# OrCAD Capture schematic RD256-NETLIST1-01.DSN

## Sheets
1 3: size A3
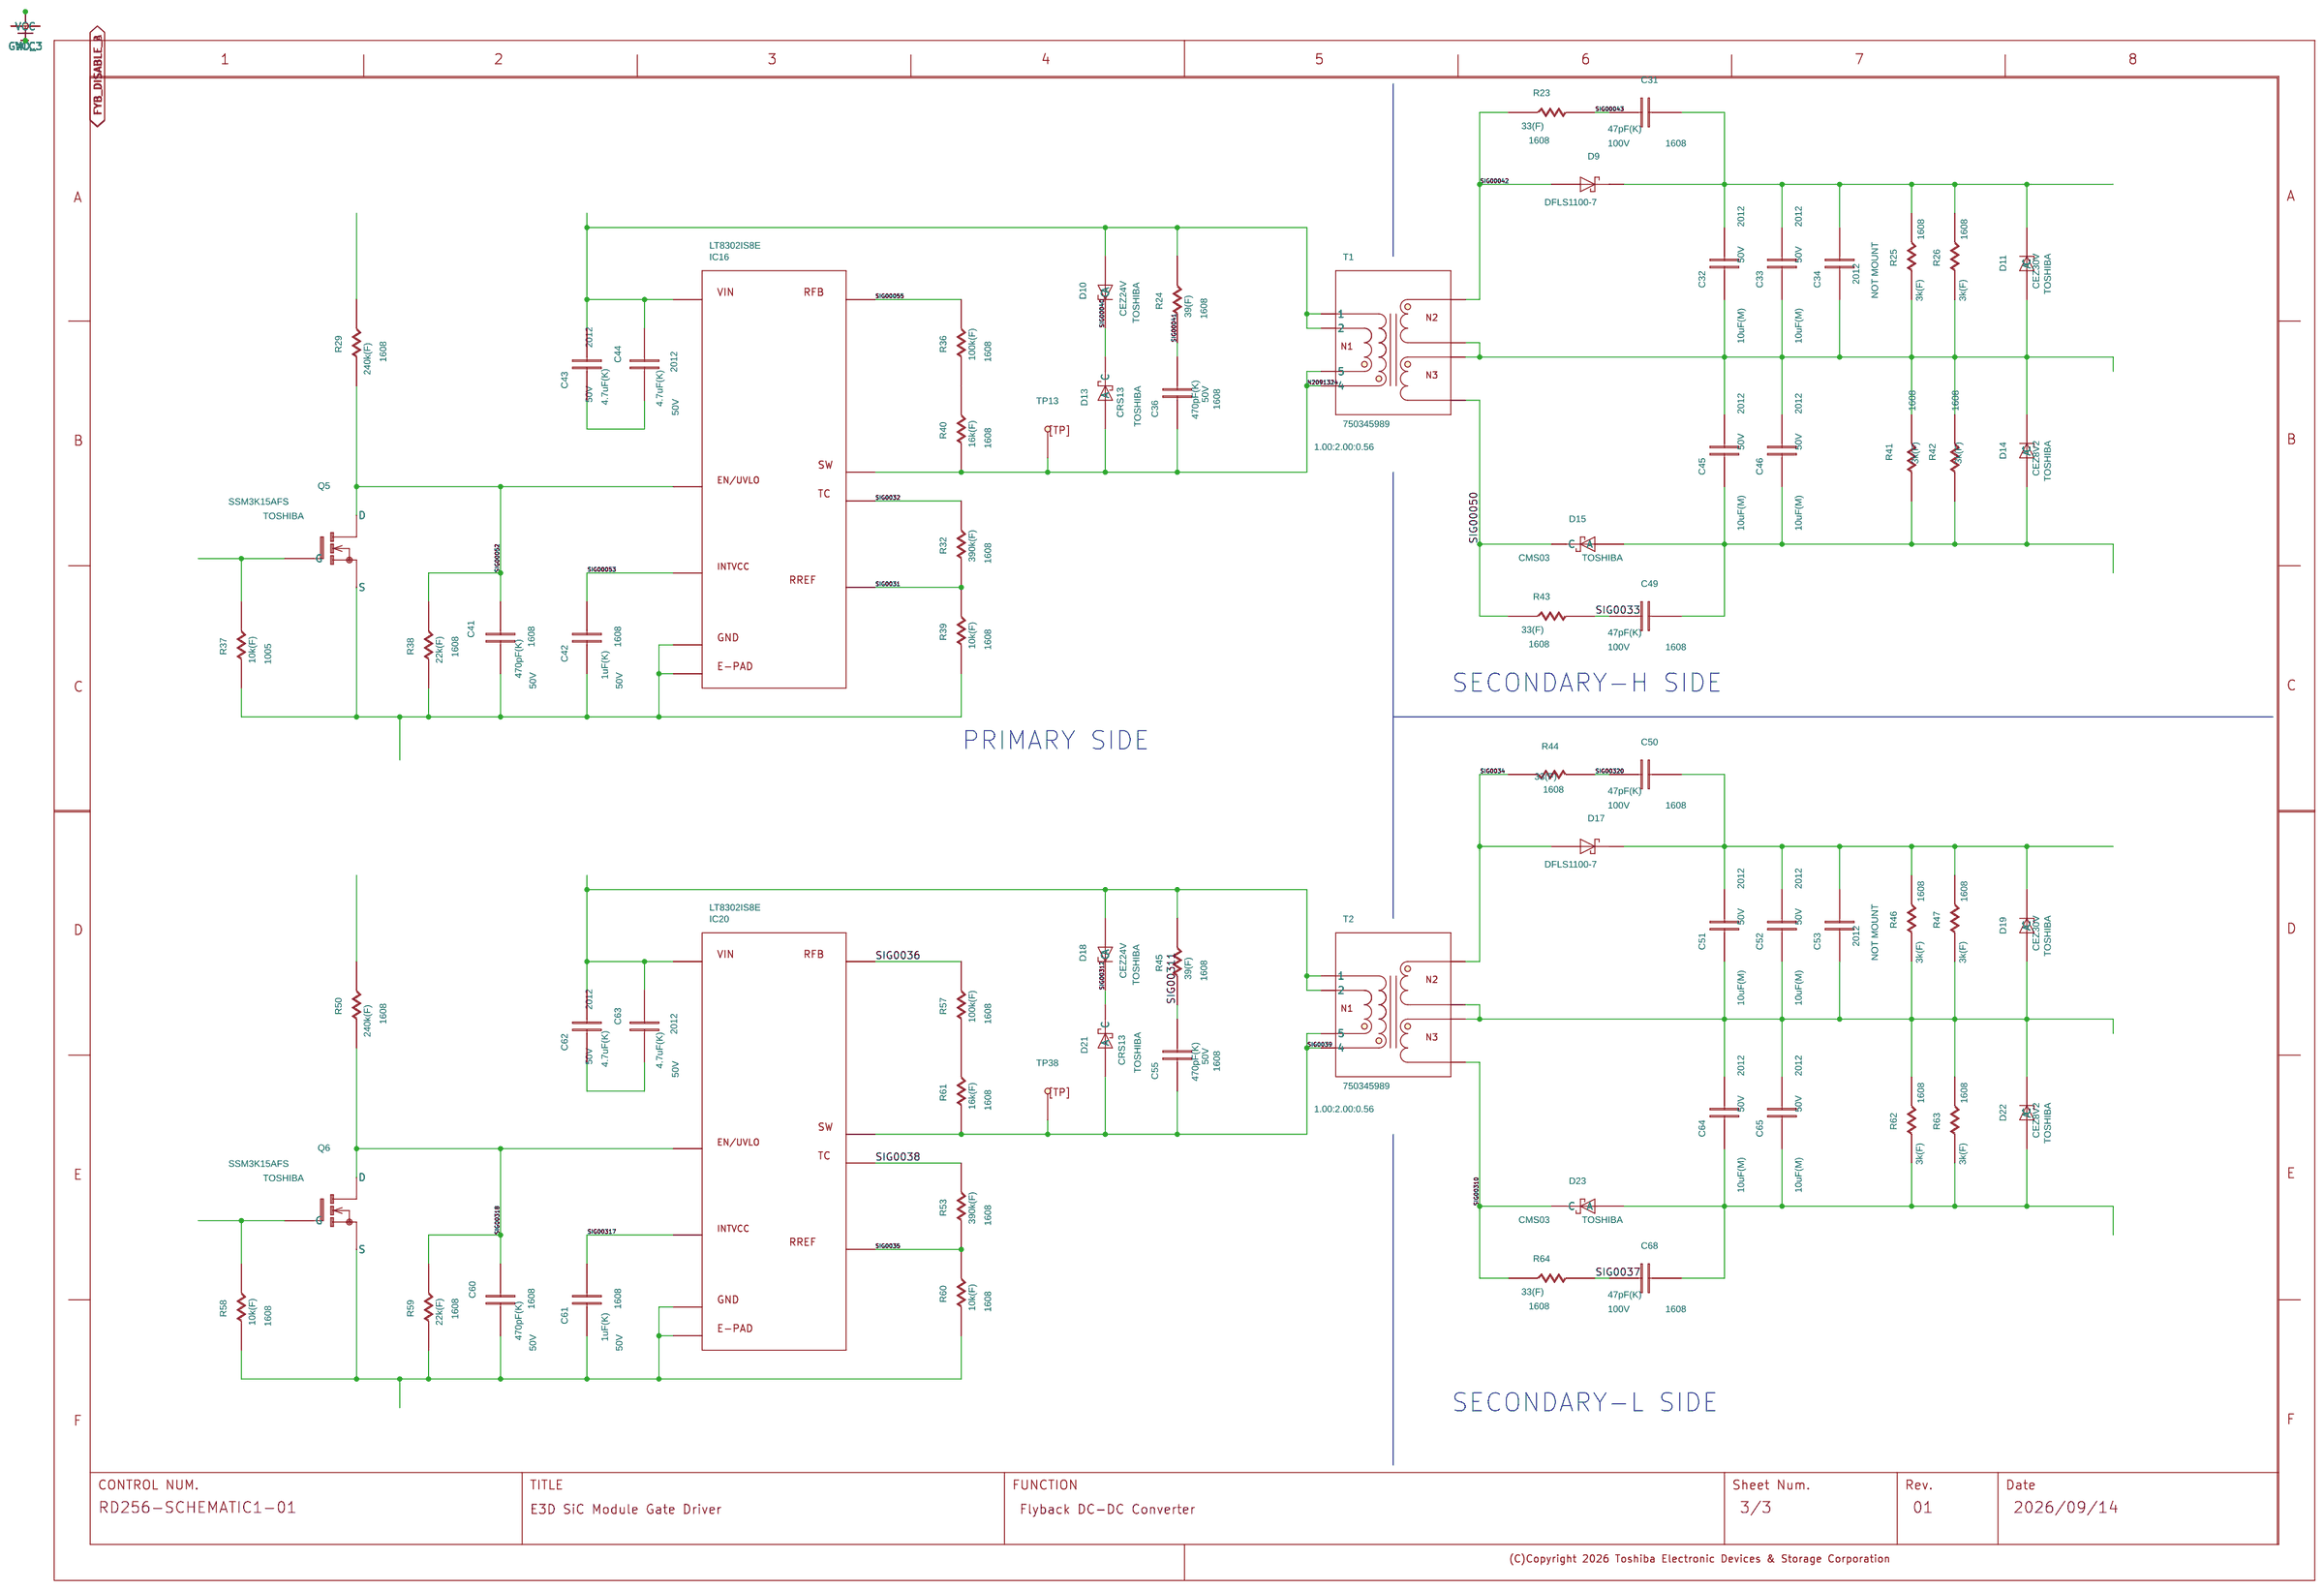
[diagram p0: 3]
2 2: size A3
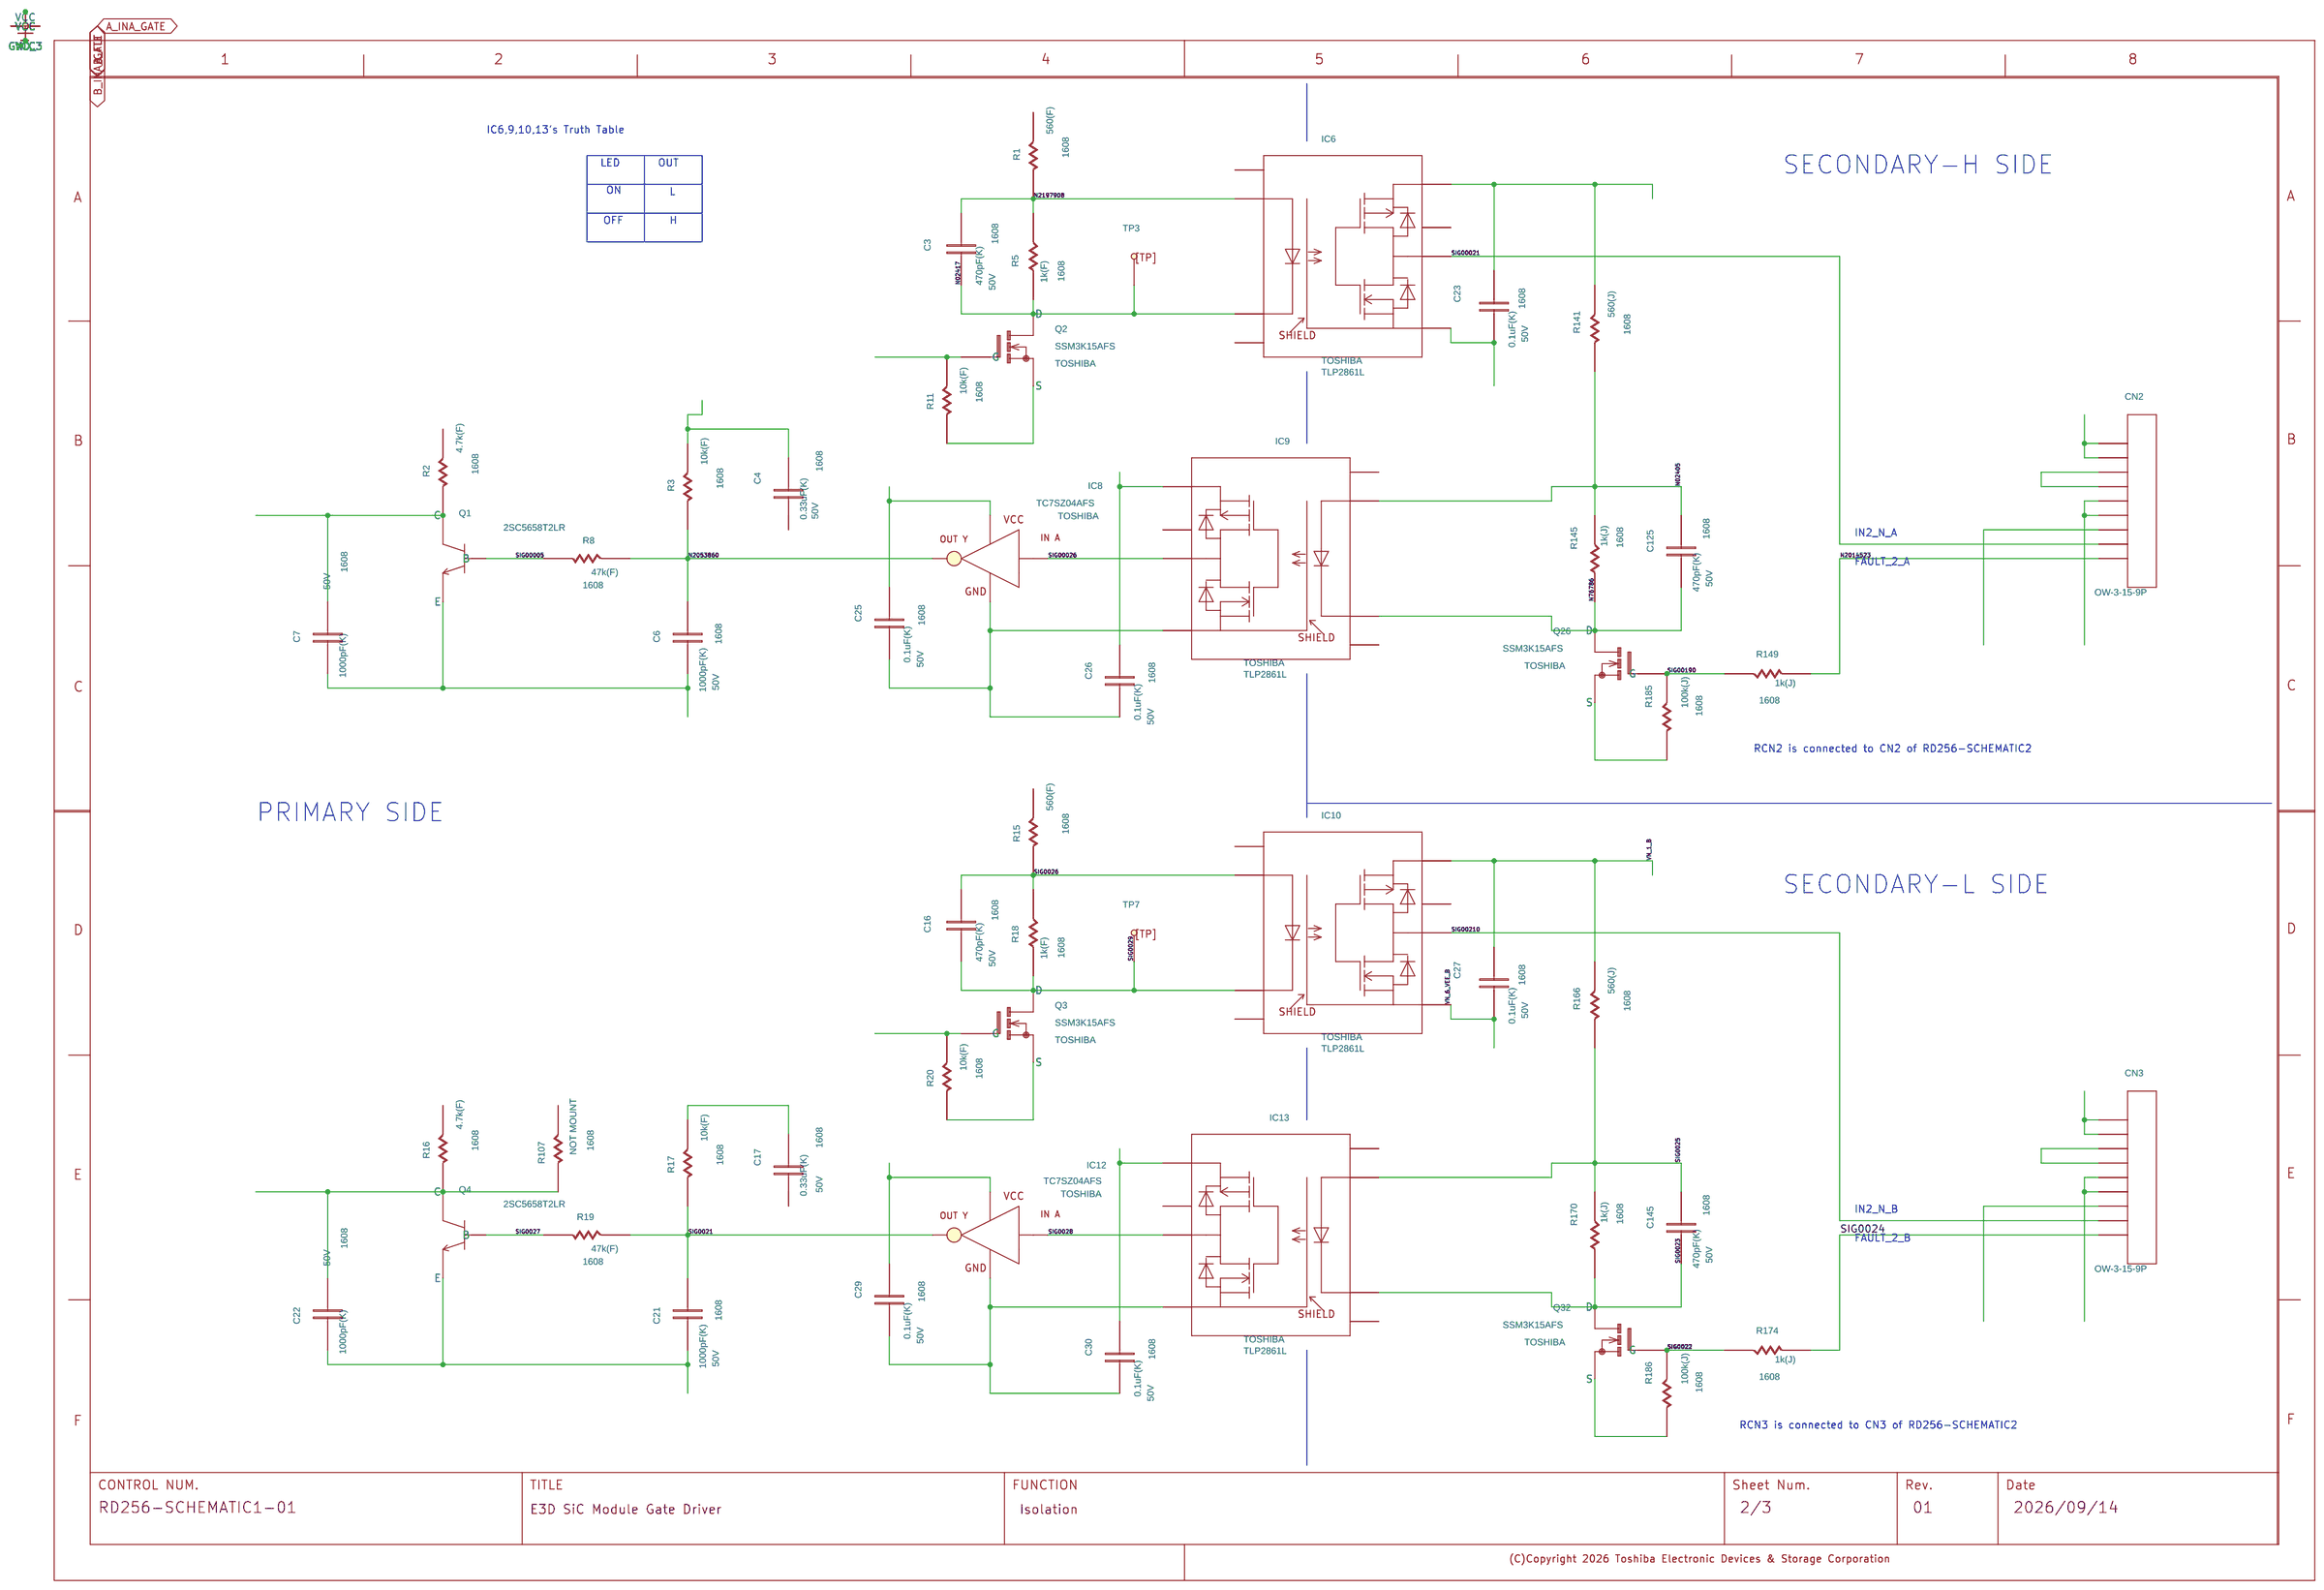
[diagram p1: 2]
3 1: size A3
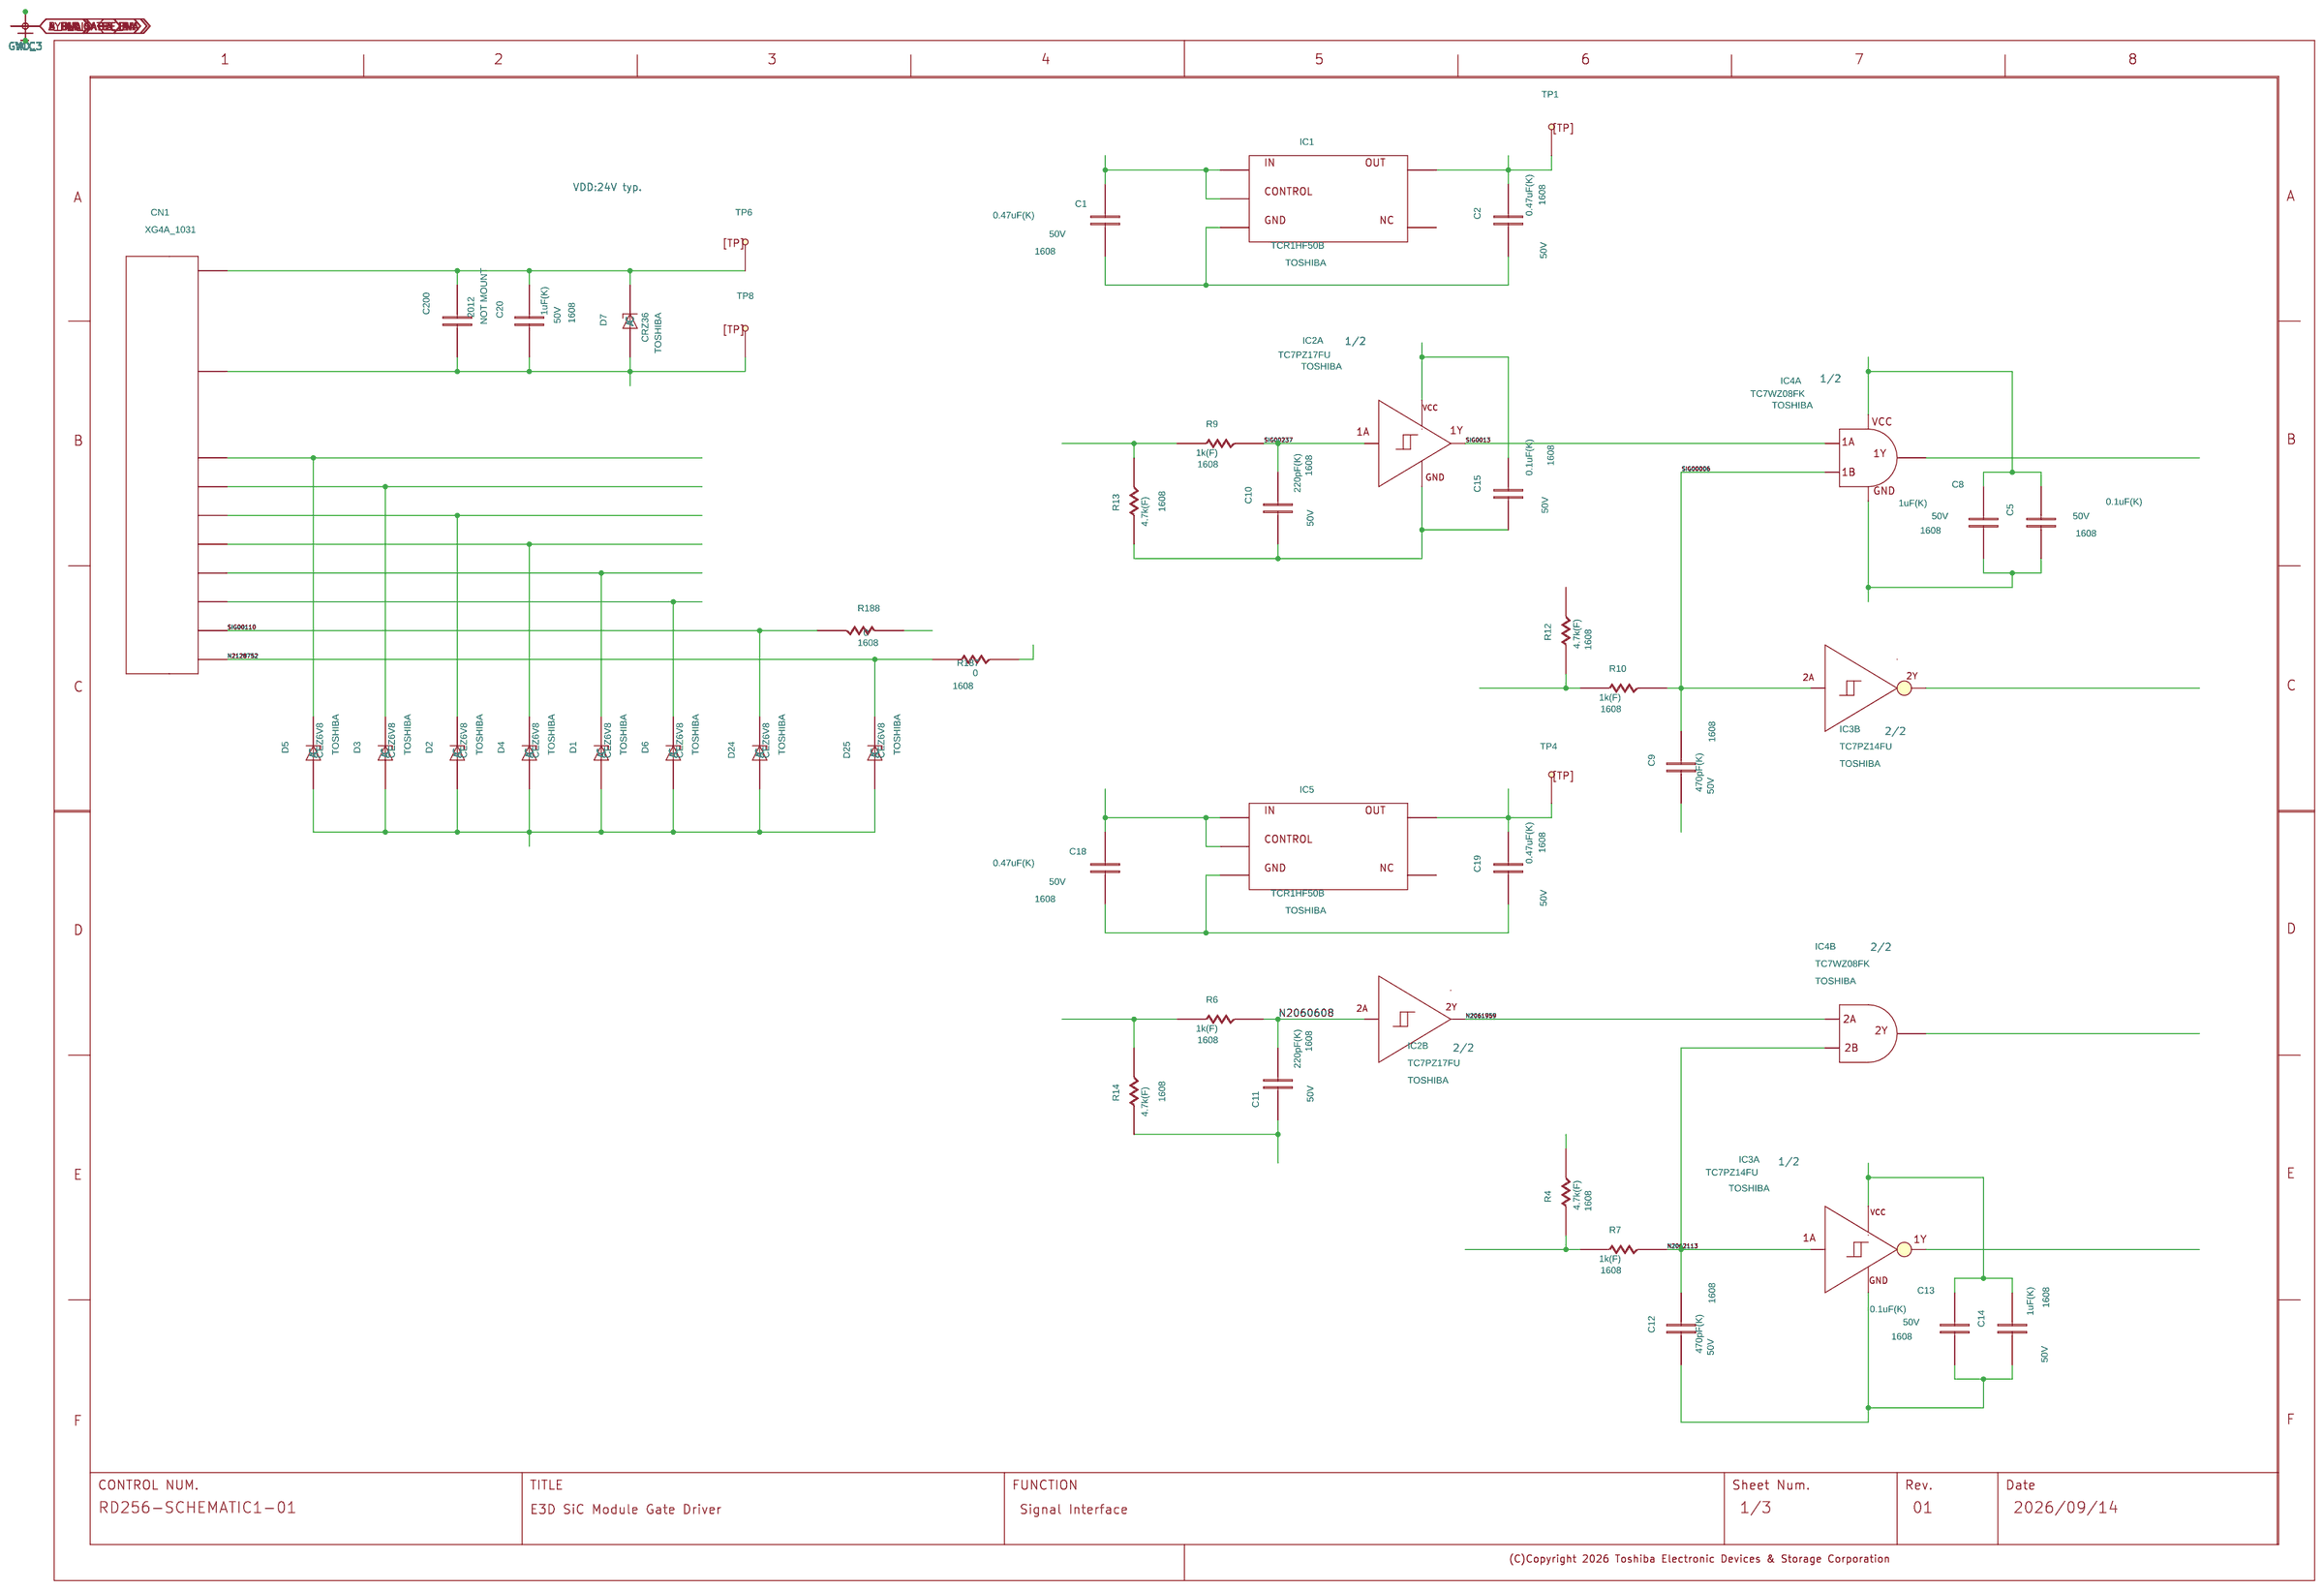
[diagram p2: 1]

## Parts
sheet 1
C1  1n
C2  1n
C5  1n
C8  1n
C9  1n
C10  1n
C11  1n
C12  1n
C13  1n
C14  1n
C15  1n
C18  1n
C19  1n
C20  1n
C200  1n
CN1  XG4A_1031
D1  CEZ6V8
D2  CEZ6V8
D3  CEZ6V8
D4  CEZ6V8
D5  CEZ6V8
D6  CEZ6V8
D7  CRZ36
D24  CEZ6V8
D25  CEZ6V8
IC1  TCR1HF50B
IC2  TC7PZ17FU  (sections A,B)
IC3  TC7PZ17FU  (sections A,B)
IC4  TC7WZ08FK  (sections A,B)
IC5  TCR1HF50B
R4  1k
R6  1k
R7  1k
R9  1k
R10  1k
R12  1k
R13  1k
R14  1k
R187  1k
R188  1k
TP1  TP
TP4  TP
TP6  TP
TP8  TP
U?#2  WAKU_DEF100
sheet 2
C3  1n
C4  1n
C6  1n
C7  1n
C16  1n
C17  1n
C21  1n
C22  1n
C23  1n
C25  1n
C26  1n
C27  1n
C29  1n
C30  1n
C125  1n
C145  1n
CN2  CN9_2
CN3  CN9_2
IC6  TLP2861L
IC8  TC7SZ04AFS
IC9  TLP2861L
IC10  TLP2861L
IC12  TC7SZ04AFS
IC13  TLP2861L
Q1  2SC5658T2LR
Q2  SSM3K15AFS
Q3  SSM3K15AFS
Q4  2SC5658T2LR
Q26  SSM3K15AFS
Q32  SSM3K15AFS
R1  1k
R2  1k
R3  1k
R5  1k
R8  1k
R11  1k
R15  1k
R16  1k
R17  1k
R18  1k
R19  1k
R20  1k
R107  1k
R141  1k
R145  1k
R149  1k
R166  1k
R170  1k
R174  1k
R185  1k
R186  1k
TP3  TP
TP7  TP
U?#1  WAKU_DEF100
sheet 3
C31  1n
C32  1n
C33  1n
C34  1n
C36  1n
C41  1n
C42  1n
C43  1n
C44  1n
C45  1n
C46  1n
C49  1n
C50  1n
C51  1n
C52  1n
C53  1n
C55  1n
C60  1n
C61  1n
C62  1n
C63  1n
C64  1n
C65  1n
C68  1n
D9  DFLS1100-7
D10  CEZ24V
D11  CEZ30V
D13  CRS13
D14  CEZ30V
D15  CMS03
D17  DFLS1100-7
D18  CEZ24V
D19  CEZ30V
D21  CRS13
D22  CEZ30V
D23  CMS03
IC16  LT8302IS8E
IC20  LT8302IS8E
Q5  SSM3K15AFS
Q6  SSM3K15AFS
R23  1k
R24  1k
R25  1k
R26  1k
R29  1k
R32  1k
R36  1k
R37  1k
R38  1k
R39  1k
R40  1k
R41  R
R42  R
R43  1k
R44  R
R45  1k
R46  1k
R47  1k
R50  1k
R53  1k
R57  1k
R58  1k
R59  1k
R60  1k
R61  1k
R62  1k
R63  1k
R64  1k
T1  750345989
T2  750345989
TP13  TP
TP38  TP
U?#3  WAKU_DEF100

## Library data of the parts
C1 C18 = C: COMPONENTTYPE: 4; INSTANCENAME: INS1386363; SIZECODESMD: 1608; VAL1: 0.47uF(K); VAL2: 50V
C2 C19 = C: COMPONENTTYPE: 4; INSTANCENAME: INS1386331; SIZECODESMD: 1608; VAL1: 0.47uF(K); VAL2: 50V
C5 C15 = C: COMPONENTTYPE: 4; INSTANCENAME: INS1386793; SIZECODESMD: 1608; VAL1: 0.1uF(K); VAL2: 50V
C8 = C: COMPONENTTYPE: 4; INSTANCENAME: INS1386091; SIZECODESMD: 1608; VAL1: 1uF(K); VAL2: 50V
C9 C12 = C: COMPONENTTYPE: 4; INSTANCENAME: INS1386155; SIZECODESMD: 1608; VAL1: 470pF(K); VAL2: 50V
C10 C11 = C: COMPONENTTYPE: 4; INSTANCENAME: INS1386019; SIZECODESMD: 1608; VAL1: 220pF(K); VAL2: 50V
C13 = C: COMPONENTTYPE: 4; INSTANCENAME: INS1386091; SIZECODESMD: 1608; VAL1: 0.1uF(K); VAL2: 50V
C14 = C: COMPONENTTYPE: 4; INSTANCENAME: INS1386793; SIZECODESMD: 1608; VAL1: 1uF(K); VAL2: 50V
C20 = C: COMPONENTTYPE: 4; INSTANCENAME: INS1386685; SIZECODESMD: 1608; VAL1: 1uF(K); VAL2: 50V
C200 = C: COMPONENTTYPE: 4; INSTANCENAME: INS2126613; NOT MOUNT: NOT MOUNT; NOTMOUNT: NOT MOUNT; SIZECODESMD: 2012
CN1 = XG4A_1031_1: COMPONENTTYPE: 4
D1-D6 D24 D25 = CEZ6V8: COMPONENTTYPE: 4; INSTANCENAME: INS1385789; USERCOMPTEXT3: TOSHIBA
D7 = CRZ36: COMPONENTTYPE: 4; INSTANCENAME: INS1385571; USERCOMPTEXT3: TOSHIBA
IC1 IC5 = TCR1HF50B: COMPONENTTYPE: 4; INSTANCENAME: INS1386243; USERCOMPTEXT3: TOSHIBA
IC2 = TC7PZ17FU_2: COMPONENTTYPE: 8; CaptureCellPackProp: TC7PZ17FU_2A; FUNCN: TC7PZ17FU_1; INSTANCENAME: INS2115366; USERCOMPTEXT3: TOSHIBA
IC3 = TC7PZ14FU_2: COMP: TC7PZ14FU; COMPONENTTYPE: 8; CaptureCellPackProp: TC7PZ14FU_2B; INSTANCENAME: INS2116193; USERCOMPTEXT3: TOSHIBA; VAL3: TC7PZ14FU
IC4 = TC7WZ08FK_1: COMPONENTTYPE: 8; CaptureCellPackProp: TC7WZ08FK_1A; INSTANCENAME: INS2116618; USERCOMPTEXT3: TOSHIBA
R4 R12 = R: COMPONENTTYPE: 4; INSTANCENAME: INS1387005; SIZECODESMD: 1608; VAL1: 4.7k(F); VAL2: 100mW
R6 R7 R9 R10 = R: COMPONENTTYPE: 4; INSTANCENAME: INS1387005; SIZECODESMD: 1608; VAL1: 1k(F); VAL2: 100mW
R13 R14 = R: COMPONENTTYPE: 4; INSTANCENAME: INS2060849; SIZECODESMD: 1608; VAL1: 4.7k(F); VAL2: 100mW
R187 = R: COMPONENTTYPE: 4; INSTANCENAME: INS2126667; SIZECODESMD: 1608; VAL1: 0
R188 = R: COMPONENTTYPE: 4; INSTANCENAME: INS2126643; SIZECODESMD: 1608; VAL1: 0
TP1 = TP: COMPONENTKIND: 127; COMPONENTTYPE: 4; INSTANCENAME: INS1385435
TP4 = TP: COMPONENTKIND: 127; COMPONENTTYPE: 4; INSTANCENAME: INS2191044
TP6 = TP: COMPONENTKIND: 127; COMPONENTTYPE: 4; INSTANCENAME: INS1386079
TP8 = TP: COMPONENTKIND: 127; COMPONENTTYPE: 4; INSTANCENAME: INS1386853
U?#2 = WAKU_DEF100: COMPONENTTYPE: 2; CONTROL NUM: RD256-SCHEMATIC-0; DATE: 2026/09/14; DRAWINGNUMBER: RD256-SCHEMATIC1-01; FUNCTION: Signal Interface; NUMBER DEVICES IN PACKAGE: 1; PIN NAMES ROTATE: True; PIN NAMES VISIBLE: False; PIN NUMBERS VISIBLE: False; REV: 00; REVISION: 01; SAVEAREA0: -63393,-16950,474261,314592; SAVECOUNT: 4; SHEET NUM: X/X; SHEETNUMBER: 1/3; SHTSAVECOUNT: 49; TITLE: E3D SiC Module Gate Driver; UPDATEDATE: 2019/02/14; UPDATETIME: 15:37:05; UPDATEUSER: d5009410
C3 C16 = C: COMPONENTTYPE: 4; INSTANCENAME: INS2054894; SIZECODESMD: 1608; VAL1: 470pF(K); VAL2: 50V
C4 C17 = C: COMPONENTTYPE: 4; INSTANCENAME: INS2053830; SIZECODESMD: 1608; VAL1: 0.33uF(K); VAL2: 50V
C6 C7 C21 C22 = C: COMPONENTTYPE: 4; INSTANCENAME: INS2053916; SIZECODESMD: 1608; VAL1: 1000pF(K); VAL2: 50V
C23 C27 = C: COMPONENTTYPE: 4; INSTANCENAME: INS1388174; SIZECODESMD: 1608; VAL1: 0.1uF(K); VAL2: 50V
C25 C26 C29 C30 = C: COMPONENTTYPE: 4; INSTANCENAME: INS1387946; SIZECODESMD: 1608; VAL1: 0.1uF(K); VAL2: 50V
C125 C145 = C: COMPONENTTYPE: 4; INSTANCENAME: INS2013765; SIZECODESMD: 1608; VAL1: 470pF(K); VAL2: 50V
CN2 CN3 = CN9_1: COMP: OW-3-15-9P; COMPONENTTYPE: 4; INSTANCENAME: INS2085144; VAL3: OW-3-15-9P
IC6 IC9 IC10 IC13 = TLP2861: COMPONENTTYPE: 4; USERCOMPTEXT3: TOSHIBA
IC8 IC12 = TC7SZ04AFS: COMPONENTTYPE: 4; INSTANCENAME: INS2077754; USERCOMPTEXT3: TOSHIBA
Q1 Q4 = 2SC5658J: COMPONENTTYPE: 4; INSTANCENAME: INS2053972
Q2 Q3 = SSM3K15AFS: COMPONENTTYPE: 4; INSTANCENAME: INS2055002; USERCOMPTEXT3: TOSHIBA
Q26 Q32 = SSM3K15AFS: COMPONENTTYPE: 4; INSTANCENAME: INS2013847; USERCOMPTEXT3: TOSHIBA
R1 R15 = R: COMPONENTTYPE: 4; INSTANCENAME: INS2053752; SIZECODESMD: 1608; VAL1: 560(F); VAL2: 100mW
R2 R16 = R: COMPONENTTYPE: 4; INSTANCENAME: INS2053752; SIZECODESMD: 1608; VAL1: 4.7k(F); VAL2: 100mW
R3 R11 R17 R20 = R: COMPONENTTYPE: 4; INSTANCENAME: INS2053752; SIZECODESMD: 1608; VAL1: 10k(F); VAL2: 100mW
R5 R18 = R: COMPONENTTYPE: 4; INSTANCENAME: INS2054922; SIZECODESMD: 1608; VAL1: 1k(F); VAL2: 100mW
R8 R19 = R: COMPONENTTYPE: 4; INSTANCENAME: INS2053892; SIZECODESMD: 1608; VAL1: 47k(F); VAL2: 100mW
R107 = R: COMPONENTTYPE: 4; INSTANCENAME: INS2053752; NOTMOUNT: NOT MOUNT; SIZECODESMD: 1608
R141 R166 = R: COMPONENTTYPE: 4; INSTANCENAME: INS2013711; SIZECODESMD: 1608; VAL1: 560(J); VAL2: 100mW
R145 R149 R170 R174 = R: COMPONENTTYPE: 4; INSTANCENAME: INS2013869; SIZECODESMD: 1608; VAL1: 1k(J); VAL2: 100mW
R185 R186 = R: COMPONENTTYPE: 4; INSTANCENAME: INS2014404; SIZECODESMD: 1608; VAL1: 100k(J); VAL2: 100mW
TP3 TP7 = TP: COMPONENTKIND: 127; COMPONENTTYPE: 4; INSTANCENAME: INS2054950
U?#1 = WAKU_DEF100: COMPONENTTYPE: 2; CONTROL NUM: RD256-SCHEMATIC-0; DATE: 2026/09/14; DRAWINGNUMBER: RD256-SCHEMATIC1-01; FUNCTION: Isolation; NUMBER DEVICES IN PACKAGE: 1; PIN NAMES ROTATE: True; PIN NAMES VISIBLE: False; PIN NUMBERS VISIBLE: False; REV: 00; REVISION: 01; SAVEAREA0: -63393,-16950,474261,314592; SAVECOUNT: 4; SHEET NUM: X/X; SHEETNUMBER: 2/3; SHTSAVECOUNT: 37; TITLE: E3D SiC Module Gate Driver; UPDATEDATE: 2019/02/14; UPDATETIME: 15:37:05; UPDATEUSER: d5009410
C31 C49 C50 C68 = C: COMPONENTTYPE: 4; INSTANCENAME: INS2090890; SIZECODESMD: 1608; VAL1: 47pF(K); VAL2: 100V
C32 C33 C45 C46 C51 C52 C64 C65 = C: COMPONENTTYPE: 4; INSTANCENAME: INS2091140; SIZECODESMD: 2012; VAL1: 10uF(M); VAL2: 50V
C34 C53 = C: COMPONENTTYPE: 4; INSTANCENAME: INS2091140; NOTMOUNT: NOT MOUNT; SIZECODESMD: 2012
C36 C55 = C: COMPONENTTYPE: 4; INSTANCENAME: INS2091518; SIZECODESMD: 1608; VAL1: 470pF(K); VAL2: 50V
C41 C60 = C: COMPONENTTYPE: 4; INSTANCENAME: INS2092186; SIZECODESMD: 1608; VAL1: 470pF(K); VAL2: 50V
C42 C61 = C: COMPONENTTYPE: 4; INSTANCENAME: INS2092186; SIZECODESMD: 1608; VAL1: 1uF(K); VAL2: 50V
C43 C62 = C: COMPONENTTYPE: 4; INSTANCENAME: INS2092266; SIZECODESMD: 2012; VAL1: 4.7uF(K); VAL2: 50V
C44 C63 = C: COMPONENTTYPE: 4; INSTANCENAME: INS2091518; SIZECODESMD: 2012; VAL1: 4.7uF(K); VAL2: 50V
D9 D17 = DFLS1100: COMPONENTTYPE: 4; INSTANCENAME: INS2090946
D10 D18 = CEZ24V: COMPONENTTYPE: 4; INSTANCENAME: INS2091294; USERCOMPTEXT3: TOSHIBA
D11 D19 = CEZ30V: COMPONENTTYPE: 4; INSTANCENAME: INS2091274; USERCOMPTEXT3: TOSHIBA
D13 D21 = CRS13: COMPONENTTYPE: 4; INSTANCENAME: INS2091426; USERCOMPTEXT3: TOSHIBA
D14 = CEZ30V: COMP: CEZ8V2; COMPONENTTYPE: 4; INSTANCENAME: INS2091274; USERCOMPTEXT3: TOSHIBA; VAL3: CEZ8V2
D15 D23 = CMS03: COMPONENTTYPE: 4; INSTANCENAME: INS2091824; USERCOMPTEXT3: TOSHIBA
D22 = CEZ30V: COMPONENTTYPE: 4; INSTANCENAME: INS2091274; USERCOMPTEXT3: TOSHIBA; VAL3: CEZ8V2
IC16 IC20 = LT8302: COMPONENTTYPE: 4; INSTANCENAME: INS2091844
Q5 Q6 = SSM3K15AFS: COMPONENTTYPE: 4; INSTANCENAME: INS2091762; USERCOMPTEXT3: TOSHIBA
R23 R43 R64 = R: COMPONENTTYPE: 4; INSTANCENAME: INS2090866; SIZECODESMD: 1608; VAL1: 33(F); VAL2: 100mW
R24 R45 = R: COMPONENTTYPE: 4; INSTANCENAME: INS2091678; SIZECODESMD: 1608; VAL1: 39(F); VAL2: 100mW
R25 R26 R46 R47 R62 R63 = R: COMPONENTTYPE: 4; INSTANCENAME: INS2091226; SIZECODESMD: 1608; VAL1: 3k(F); VAL2: 100mW
R29 R50 = R: COMPONENTTYPE: 4; INSTANCENAME: INS2091678; SIZECODESMD: 1608; VAL1: 240k(F); VAL2: 100mW
R32 R53 = R: COMPONENTTYPE: 4; INSTANCENAME: INS2091678; SIZECODESMD: 1608; VAL1: 390k(F); VAL2: 100mW
R36 R57 = R: COMPONENTTYPE: 4; INSTANCENAME: INS2091678; SIZECODESMD: 1608; VAL1: 100k(F); VAL2: 100mW
R37 = R: COMPONENTTYPE: 4; INSTANCENAME: INS2091678; SIZECODESMD: 1005; VAL1: 10k(F); VAL2: 100mW
R38 R59 = R: COMPONENTTYPE: 4; INSTANCENAME: INS2091678; SIZECODESMD: 1608; VAL1: 22k(F); VAL2: 100mW
R39 R58 R60 = R: COMPONENTTYPE: 4; INSTANCENAME: INS2091678; SIZECODESMD: 1608; VAL1: 10k(F); VAL2: 100mW
R40 R61 = R: COMPONENTTYPE: 4; INSTANCENAME: INS2091678; SIZECODESMD: 1608; VAL1: 16k(F); VAL2: 100mW
R41 R42 = R: COMPONENTTYPE: 4; SAVECOUNT: 0; SIZECODESMD: 1608; VAL1: 3k(F); VAL2: 100mW
R44 = R: COMPONENTTYPE: 4; SAVECOUNT: 0; SIZECODESMD: 1608; VAL1: 33(F); VAL2: 100mW
T1 T2 = 750345989_2: COMPONENTTYPE: 4; INSTANCENAME: INS2101815; VAL1: 1.00:2.00:0.56; WINDING RATIO: 1.00:2.00:0.56
TP13 TP38 = TP: COMPONENTKIND: 127; COMPONENTTYPE: 4; INSTANCENAME: INS2091728
U?#3 = WAKU_DEF100: COMPONENTTYPE: 2; CONTROL NUM: RD256-SCHEMATIC-0; DATE: 2026/09/14; DRAWINGNUMBER: RD256-SCHEMATIC1-01; FUNCTION: Flyback DC-DC Converter; NUMBER DEVICES IN PACKAGE: 1; PIN NAMES ROTATE: True; PIN NAMES VISIBLE: False; PIN NUMBERS VISIBLE: False; REV: 00; REVISION: 01; SAVEAREA0: -63393,-16950,474261,314592; SAVECOUNT: 4; SHEET NUM: X/X; SHEETNUMBER: 3/3; SHTSAVECOUNT: 37; TITLE: E3D SiC Module Gate Driver; UPDATEDATE: 2019/02/14; UPDATETIME: 15:37:05; UPDATEUSER: d5009410

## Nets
GND: C1.1 C2.1 C4.1 C5.1 C6.1 C7.1 C8.1 C9.1 C10.1 C11.1 C12.1 C13.1 C14.1 C15.1 C17.1 C18.1 C19.1 C20.1 C21.1 C22.1 C25.1 C26.1 C29.1 C30.1 C41.1 C42.1 C43.1 C44.1 C60.1 C61.1 C62.1 C63.1 C200.1 CN1.1 D1.2(A) D2.2(A) D3.2(A) D4.2(A) D5.2(A) D6.2(A) D7.1(A) D24.2(A) D25.2(A) IC1.2 IC2.2 IC3.2 IC4.4 IC5.2 IC8.2 IC9.5 IC12.2 IC13.5 IC16.4 IC16.9 IC20.4 IC20.9 Q1.2(E) Q2.2(S) Q3.2(S) Q4.2(E) Q5.2(S) Q6.2(S) R11.1 R13.1 R14.1 R20.1 R37.1 R38.1 R39.1 R58.1 R59.1 R60.1 TP8.1
VDD: C1.2 C18.2 C20.2 C43.2 C44.2 C62.2 C63.2 C200.2 CN1.2 D7.2(C) D10.2(A) D18.2(A) IC1.1 IC1.3 IC5.1 IC5.3 IC16.3 IC20.3 R24.2 R29.2 R45.2 R50.2 T1.4(1) T1.5(2) T2.4(1) T2.5(2) TP6.1
A_ENA: CN1.7 D1.1(C) R10.1 R12.1
A_FLT: C7.2 CN1.8 D6.1(C) Q1.3(C) R2.1
A_INA: CN1.5 D2.1(C) R9.1 R13.2
A_INA_GATE: IC4.7 Q2.1(G) R11.2
B_ENA: CN1.6 D4.1(C) R4.1 R7.1
B_FLT: C22.2 CN1.3 D5.1(C) Q4.3(C) R16.1 R107.1
B_INA: CN1.4 D3.1(C) R6.1 R14.2
B_INA_GATE: IC4.3 Q3.1(G) R20.2
FYB_DISABLE_A: IC3.4 Q5.1(G) R37.2
FYB_DISABLE_B: IC3.6 Q6.1(G) R58.2
SIG00005: Q1.1(B) R8.1
SIG00006: C9.2 IC3.3 IC4.2 R10.2
SIG0013: IC2.6 IC4.1
SIG0021: C21.2 IC12.4 R17.1 R19.2
SIG00021: CN2.8 IC6.6
SIG0022: Q32.1(G) R174.2 R186.2
SIG0023: C145.1 IC13.3 Q32.3(D) R170.1
SIG0024: CN3.9 R174.1
SIG0025: C145.2 IC13.2 R166.1 R170.2
SIG00026: IC8.1 IC9.6
SIG0026: C16.2 IC10.2 R15.1 R18.2
SIG0027: Q4.1(B) R19.1
SIG0028: IC12.1 IC13.6
SIG0029: C16.1 IC10.3 Q3.3(D) R18.1 TP7.1
SIG0031: IC16.7 R32.1 R39.2
SIG0032: IC16.8 R32.2
SIG0033: C49.2 R43.1
SIG0034: D17.A R44.2 T2.15
SIG0035: IC20.7 R53.1 R60.2
SIG0036: IC20.6 R57.2
SIG0037: C68.2 R64.1
SIG0038: IC20.8 R53.2
SIG0039: C55.1 D21.1(A) IC20.5 R61.1 T2.1(4) T2.2(5) TP38.1
SIG00040: D10.1(C) D13.2(C)
SIG00041: C36.2 R24.1
SIG00042: D9.A R23.2 T1.15
SIG00043: C31.2 R23.1
SIG00050: D15.2(C) R43.2 T1.12
SIG00052: C41.2 IC16.1 Q5.3(D) R29.1 R38.2
SIG00053: C42.2 IC16.2
SIG00055: IC16.6 R36.2
SIG00110: CN1.9 D24.1(C) R188.2
SIG00190: Q26.1(G) R149.2 R185.2
SIG00210: CN3.8 IC10.6
SIG00237: C10.2 IC2.1 R9.2
SIG00310: D23.2(C) R64.2 T2.12
SIG00311: C55.2 R45.1
SIG00312: D18.1(C) D21.2(C)
SIG00317: C61.2 IC20.2
SIG00318: C60.2 IC20.1 Q6.3(D) R50.1 R59.2
SIG00320: C50.2 R44.1
V_0_VE_A: C32.1 C33.1 C34.1 C45.2 C46.2 CN2.3 CN2.4 D11.2(A) D14.1(C) R25.1 R26.1 R41.2 R42.2 T1.13 T1.14
V_0_VE_B: C51.1 C52.1 C53.1 C64.2 C65.2 CN3.3 CN3.4 D19.2(A) D22.1(C) R46.1 R47.1 R62.2 R63.2 T2.13 T2.14
VN_1_A: C23.2 CN2.7 IC6.8 R141.2
VN_1_B: C27.2 CN3.7 IC10.8 R166.2
VN_6_VEE_A: C23.1 C45.1 C46.1 C49.1 CN2.5 CN2.6 D14.2(A) D15.1(A) IC6.5 Q26.2(S) R41.1 R42.1 R185.1
VN_6_VEE_B: C27.1 C64.1 C65.1 C68.1 CN3.5 CN3.6 D22.2(A) D23.1(A) IC10.5 Q32.2(S) R62.1 R63.1 R186.1
VP_5_A: C2.2 C4.2 C5.2 C8.2 C13.2 C14.2 C15.2 C17.2 C19.2 C25.2 C26.2 C29.2 C30.2 IC1.5 IC2.5 IC3.5 IC4.8 IC5.5 IC8.5 IC9.8 IC12.5 IC13.8 R1.2 R2.2 R3.2 R4.2 R12.2 R15.2 R16.2 R17.2 R107.2 R187.2 R188.1 TP1.1 TP4.1
VP_24_A: C31.1 C32.2 C33.2 C34.2 CN2.1 CN2.2 D9.C D11.1(C) R25.2 R26.2
VP_24_B: C50.1 C51.2 C52.2 C53.2 CN3.1 CN3.2 D17.C D19.1(C) R46.2 R47.2
N02405: C125.2 IC9.2 R141.1 R145.2
N02417: C3.1 IC6.3 Q2.3(D) R5.1 TP3.1
N06341: R36.1 R40.2
N06342: R57.1 R61.2
N76786: C125.1 IC9.3 Q26.3(D) R145.1
N2014523: CN2.9 R149.1
N2053860: C6.2 IC8.4 R3.1 R8.2
N2060608: C11.2 IC2.3 R6.2
N2061959: IC2.4 IC4.5
N2062113: C12.2 IC3.1 IC4.6 R7.2
N2091324: C36.1 D13.1(A) IC16.5 R40.1 T1.1(4) T1.2(5) TP13.1
N2128752: CN1.10 D25.1(C) R187.1
N2197908: C3.2 IC6.2 R1.1 R5.2

Not connected (* = marked no-connect by the designer): CN1 M1 M2; IC1 4; IC5 4; IC6 1 4 7; IC8 3; IC9 1 4 7; IC10 1 4 7; IC12 3; IC13 1 4 7

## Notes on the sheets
sheet 1
- SECONDARY-H SIDE
- PRIMARY SIDE
- SECONDARY-L SIDE
sheet 2
- IC6,9,10,13's Truth Table
- LED
- OUT
- SECONDARY-H SIDE
- ON
- L
- OFF
- H
- IN2_N_A
- FAULT_2_A
- RCN2 is connected to CN2 of RD256-SCHEMATIC2
- PRIMARY SIDE
- SECONDARY-L SIDE
- IN2_N_B
- FAULT_2_B
- RCN3 is connected to CN3 of RD256-SCHEMATIC2
sheet 3
- VDD:24V typ.
- 1/2
- 1/2
- 2/2
- 2/2
- 2/2
- 1/2
